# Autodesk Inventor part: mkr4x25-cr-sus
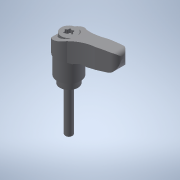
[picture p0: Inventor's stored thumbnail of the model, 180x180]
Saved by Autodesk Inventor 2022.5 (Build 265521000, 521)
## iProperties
Created: 2017-09
Part Number: mkr4x25-cr-sus
Material: 一般
Document SubType Name: Modeling
Designer: imaocorp
Density: 1 g/cm^3
Appearance: 既定
Author: imaocorp
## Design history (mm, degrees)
node "mkr4x25-cr-sus.x_t1"
node "mkr4x25-cr-sus"
node "Base1"
